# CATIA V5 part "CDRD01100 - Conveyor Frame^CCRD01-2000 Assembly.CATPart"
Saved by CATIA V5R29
Part number: CDRD01100 - Conveyor Frame^CCRD01-2000 Assembly
Definition: design
Source: Unknown
Bounding box of the stored display mesh (mm): x -54 to 4, y -4 to 134, z 0 to 2000
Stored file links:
  C:\가치같이\SmartFactory_BoxErectorConveyor\CDRD01100 - Conveyor Frame^CCRD01-2000 Assembly.CATPart
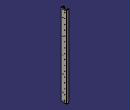
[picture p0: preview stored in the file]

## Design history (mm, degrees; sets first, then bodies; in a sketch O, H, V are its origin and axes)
Body1 "Cut-Extrude4" (main body)
  Solid1: solid without history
